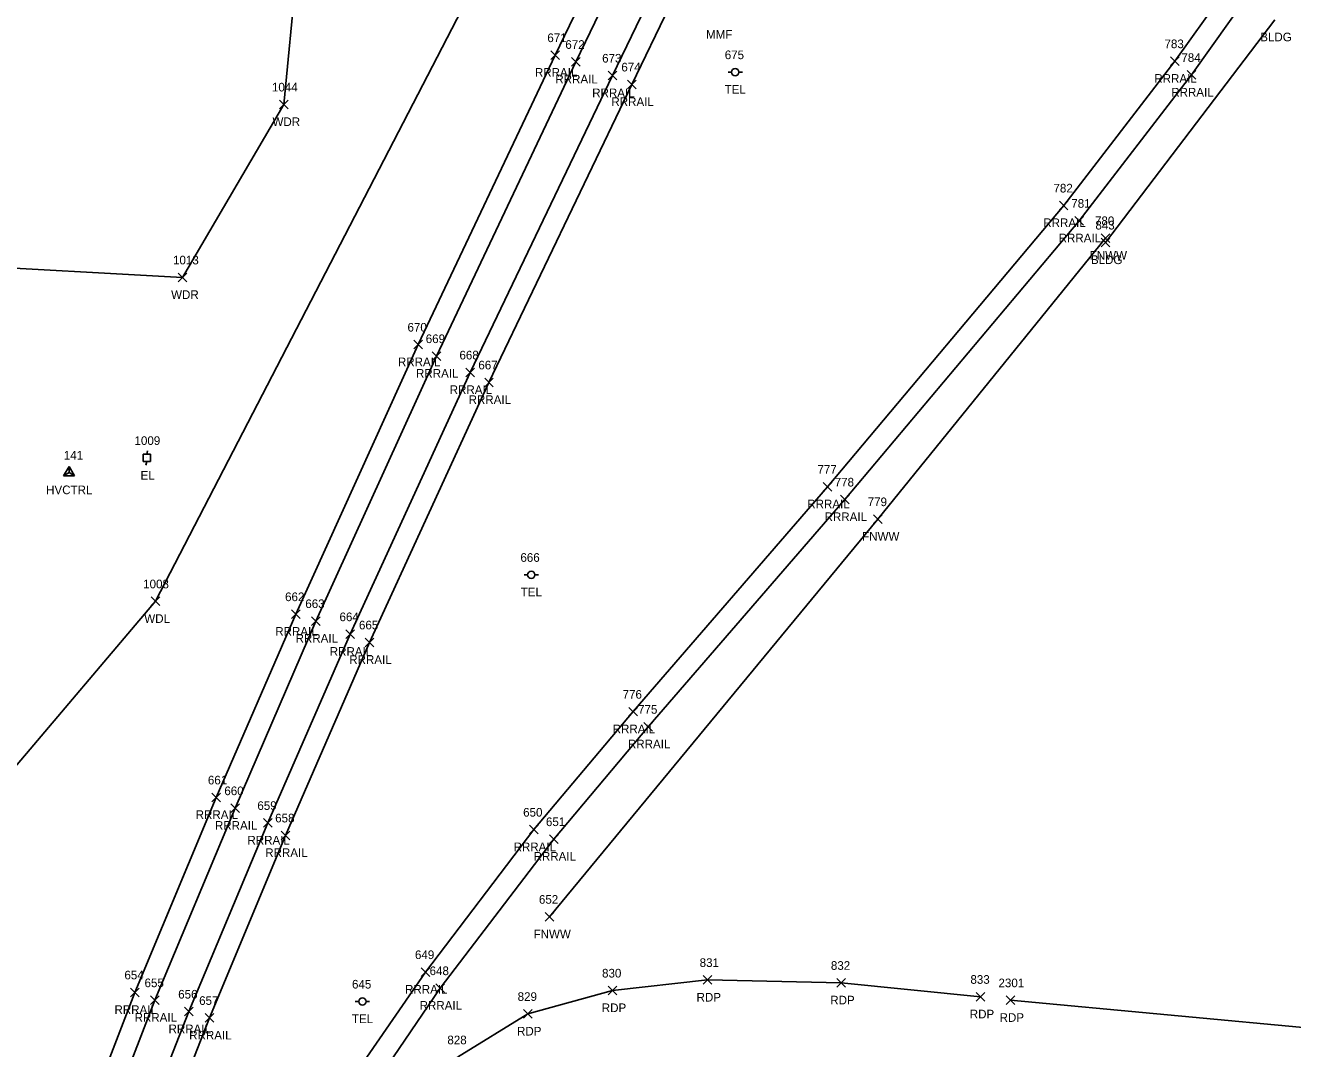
# Model space of a CAD drawing. Extents: x 1767353 to 1772625, y 740790 to 747702.
# Drawn here: x 1770332.7 to 1770625.6, y 742432.9 to 742669.5 of the extents above; entities that cross this region are included whole.
import ezdxf

# ---------------------------------------------------------------- set-up
doc = ezdxf.new("R2010")
doc.units = 0
for name, color, linetype in [('C_A', 7, 'Continuous'), ('C_I', 7, 'Continuous'), ('CPSM', 7, 'Continuous'), ('L_A', 7, 'Continuous'), ('L_I', 7, 'Continuous'), ('L_TIC', 7, 'Continuous'), ('LAWA', 7, 'Continuous'), ('LBC', 7, 'Continuous'), ('LFNC', 7, 'Continuous'), ('P_A', 7, 'Continuous'), ('P_I', 7, 'Continuous'), ('P_TIC', 7, 'Continuous'), ('PET', 7, 'Continuous'), ('R_A', 7, 'Continuous'), ('R_I', 7, 'Continuous'), ('R_TIC', 7, 'Continuous'), ('RR', 7, 'Continuous'), ('U_A', 7, 'Continuous'), ('U_I', 7, 'Continuous'), ('UEPT', 7, 'Continuous'), ('UP', 7, 'Continuous')]:
    doc.layers.add(name, color=color, linetype=linetype)

msp = doc.modelspace()

# ---------------------------------------------------------------- linework, layer by layer
at = {"layer": 'CPSM'}
for p, q in [((1770341.57, 742565.35), (1770342.82, 742567.52)), ((1770344.07, 742565.35), (1770342.82, 742567.52)), ((1770342.82, 742566.08), (1770342.82, 742567.52)), ((1770341.57, 742565.35), (1770342.82, 742566.08)), ((1770341.57, 742565.35), (1770344.07, 742565.35)), ((1770342.82, 742566.08), (1770342.82, 742566.08)), ((1770342.82, 742566.08), (1770344.07, 742565.35))]:
    msp.add_line(p, q, dxfattribs=at)
at = {"layer": 'L_TIC'}
for points in [[(1770391.48, 742650.21), (1770393.48, 742652.21)], [(1770393.48, 742650.21), (1770391.48, 742652.21)], [(1770581.39, 742619.31), (1770583.39, 742621.31)], [(1770583.39, 742619.31), (1770581.39, 742621.31)], [(1770581.39, 742618.29), (1770583.39, 742620.29)], [(1770583.39, 742618.29), (1770581.39, 742620.29)], [(1770368.05, 742610.22), (1770370.05, 742612.22)], [(1770370.05, 742610.22), (1770368.05, 742612.22)], [(1770528.77, 742554.32), (1770530.77, 742556.32)], [(1770530.77, 742554.32), (1770528.77, 742556.32)], [(1770361.8, 742535.32), (1770363.8, 742537.32)], [(1770363.8, 742535.32), (1770361.8, 742537.32)], [(1770452.83, 742462.37), (1770454.83, 742464.37)], [(1770454.83, 742462.37), (1770452.83, 742464.37)]]:
    msp.add_lwpolyline(points, dxfattribs=at)
at = {"layer": 'LAWA'}
for points in [[(1770306.48, 742507.29), (1770316.18, 742614.11), (1770369.05, 742611.22), (1770392.48, 742651.21), (1770395.28, 742680.85), (1770432.3, 742733.17), (1770478.55, 742800.68), (1770491.83, 742862.01), (1770523.03, 742843.62)], [(1770306.48, 742507.29), (1770329.16, 742496.59), (1770362.8, 742536.32), (1770458.24, 742720.87), (1770495.95, 742787.49), (1770523.03, 742843.62)]]:
    msp.add_lwpolyline(points, dxfattribs=at)
at = {"layer": 'LBC'}
msp.add_lwpolyline([(1770582.39, 742619.29), (1770621.54, 742670.81)], dxfattribs=at)
at = {"layer": 'LFNC'}
msp.add_lwpolyline([(1770453.83, 742463.37), (1770529.77, 742555.32), (1770582.39, 742620.31)], dxfattribs=at)
at = {"layer": 'P_TIC'}
for points in [[(1770489.36, 742447.75), (1770491.36, 742449.75)], [(1770491.36, 742447.75), (1770489.36, 742449.75)], [(1770467.46, 742445.31), (1770469.46, 742447.31)], [(1770469.46, 742445.31), (1770467.46, 742447.31)], [(1770520.27, 742447.09), (1770522.27, 742449.09)], [(1770522.27, 742447.09), (1770520.27, 742449.09)], [(1770552.51, 742443.86), (1770554.51, 742445.86)], [(1770554.51, 742443.86), (1770552.51, 742445.86)], [(1770559.4, 742443.06), (1770561.4, 742445.06)], [(1770561.4, 742443.06), (1770559.4, 742445.06)], [(1770447.87, 742439.9), (1770449.87, 742441.9)], [(1770449.87, 742439.9), (1770447.87, 742441.9)]]:
    msp.add_lwpolyline(points, dxfattribs=at)
at = {"layer": 'PET'}
for points in [[(1770243.74, 741939.41), (1770255.24, 741954.28), (1770270.92, 742018.28), (1770293.62, 742096.86), (1770309.99, 742145.51), (1770335.13, 742217.35), (1770370.55, 742306.75), (1770390.86, 742357.46), (1770403.22, 742384.01), (1770418.01, 742412.4), (1770432.62, 742430.87), (1770448.87, 742440.9), (1770468.46, 742446.31), (1770490.36, 742448.75), (1770521.27, 742448.09), (1770553.51, 742444.86)], [(1770560.4, 742444.06), (1770632.97, 742437.3)]]:
    msp.add_lwpolyline(points, dxfattribs=at)
at = {"layer": 'R_TIC'}
for points in [[(1770454.2, 742661.62), (1770456.2, 742663.62)], [(1770456.2, 742661.62), (1770454.2, 742663.62)], [(1770458.92, 742660.06), (1770460.92, 742662.06)], [(1770460.92, 742660.06), (1770458.92, 742662.06)], [(1770597.36, 742660.22), (1770599.36, 742662.22)], [(1770599.36, 742660.22), (1770597.36, 742662.22)], [(1770467.44, 742656.89), (1770469.44, 742658.89)], [(1770469.44, 742656.89), (1770467.44, 742658.89)], [(1770601.26, 742657.04), (1770603.26, 742659.04)], [(1770603.26, 742657.04), (1770601.26, 742659.04)], [(1770471.88, 742654.84), (1770473.88, 742656.84)], [(1770473.88, 742654.84), (1770471.88, 742656.84)], [(1770571.7, 742626.85), (1770573.7, 742628.85)], [(1770573.7, 742626.85), (1770571.7, 742628.85)], [(1770575.25, 742623.32), (1770577.25, 742625.32)], [(1770577.25, 742623.32), (1770575.25, 742625.32)], [(1770422.54, 742594.68), (1770424.54, 742596.68)], [(1770424.54, 742594.68), (1770422.54, 742596.68)], [(1770426.72, 742592.02), (1770428.72, 742594.02)], [(1770428.72, 742592.02), (1770426.72, 742594.02)], [(1770434.51, 742588.24), (1770436.51, 742590.24)], [(1770436.51, 742588.24), (1770434.51, 742590.24)], [(1770438.88, 742585.94), (1770440.88, 742587.94)], [(1770440.88, 742585.94), (1770438.88, 742587.94)], [(1770517.15, 742561.81), (1770519.15, 742563.81)], [(1770519.15, 742561.81), (1770517.15, 742563.81)], [(1770521.14, 742558.86), (1770523.14, 742560.86)], [(1770523.14, 742558.86), (1770521.14, 742560.86)], [(1770394.2, 742532.35), (1770396.2, 742534.35)], [(1770396.2, 742532.35), (1770394.2, 742534.35)], [(1770398.89, 742530.75), (1770400.89, 742532.75)], [(1770400.89, 742530.75), (1770398.89, 742532.75)], [(1770406.79, 742527.71), (1770408.79, 742529.71)], [(1770408.79, 742527.71), (1770406.79, 742529.71)], [(1770411.29, 742525.82), (1770413.29, 742527.82)], [(1770413.29, 742525.82), (1770411.29, 742527.82)], [(1770472.18, 742509.79), (1770474.18, 742511.79)], [(1770474.18, 742509.79), (1770472.18, 742511.79)], [(1770475.7, 742506.31), (1770477.7, 742508.31)], [(1770477.7, 742506.31), (1770475.7, 742508.31)], [(1770375.8, 742489.97), (1770377.8, 742491.97)], [(1770377.8, 742489.97), (1770375.8, 742491.97)], [(1770380.25, 742487.48), (1770382.25, 742489.48)], [(1770382.25, 742487.48), (1770380.25, 742489.48)], [(1770387.76, 742484.07), (1770389.76, 742486.07)], [(1770389.76, 742484.07), (1770387.76, 742486.07)], [(1770391.87, 742481.18), (1770393.87, 742483.18)], [(1770393.87, 742481.18), (1770391.87, 742483.18)], [(1770449.26, 742482.52), (1770451.26, 742484.52)], [(1770451.26, 742482.52), (1770449.26, 742484.52)], [(1770453.89, 742480.33), (1770455.89, 742482.33)], [(1770455.89, 742480.33), (1770453.89, 742482.33)], [(1770424.18, 742449.58), (1770426.18, 742451.58)], [(1770426.18, 742449.58), (1770424.18, 742451.58)], [(1770357.03, 742444.88), (1770359.03, 742446.88)], [(1770359.03, 742444.88), (1770357.03, 742446.88)], [(1770427.56, 742445.86), (1770429.56, 742447.86)], [(1770429.56, 742445.86), (1770427.56, 742447.86)], [(1770361.68, 742443.08), (1770363.68, 742445.08)], [(1770363.68, 742443.08), (1770361.68, 742445.08)], [(1770369.52, 742440.44), (1770371.52, 742442.44)], [(1770371.52, 742440.44), (1770369.52, 742442.44)], [(1770374.3, 742438.98), (1770376.3, 742440.98)], [(1770376.3, 742438.98), (1770374.3, 742440.98)]]:
    msp.add_lwpolyline(points, dxfattribs=at)
at = {"layer": 'RR'}
for points in [[(1770221.78, 741982.04), (1770226.9, 742005.14), (1770231.58, 742026.58), (1770238.97, 742057.62), (1770247.46, 742091.31), (1770255.17, 742120.86), (1770262.38, 742147.12), (1770270.79, 742177.04), (1770278.58, 742203.25), (1770285.57, 742226.22), (1770292.18, 742247.12), (1770303.7, 742282.6), (1770315.3, 742316.87), (1770330.35, 742359.31), (1770344.25, 742396.26), (1770362.68, 742444.08), (1770381.25, 742488.48), (1770399.89, 742531.75), (1770427.72, 742593.02), (1770459.92, 742661.06), (1770775.2, 743314.07), (1770996.39, 743772.66), (1771192.02, 744177.67), (1771329.71, 744462.72)], [(1770217.88, 741982.89), (1770224.63, 742006.05), (1770231.58, 742026.58), (1770242.49, 742057.3), (1770253.86, 742089.03), (1770263.22, 742117.76), (1770271, 742143.83), (1770279.57, 742174.49), (1770286.79, 742199.43), (1770293.9, 742223.08), (1770300.84, 742244.95), (1770311.67, 742279.15), (1770323.34, 742314.32), (1770337.98, 742356.11), (1770351.9, 742393.8), (1770370.52, 742441.44), (1770388.76, 742485.07), (1770407.79, 742528.71), (1770435.51, 742589.24), (1770468.44, 742657.89), (1770783.17, 743309.95), (1771004.51, 743768.91), (1771200.35, 744174.24), (1771337.45, 744458.43)], [(1770217.02, 741983.21), (1770222.11, 742006.18), (1770226.99, 742028.12), (1770234.33, 742059.23), (1770242.65, 742092.71), (1770250.33, 742121.94), (1770257.59, 742148.49), (1770265.95, 742178.19), (1770273.77, 742204.67), (1770280.68, 742227.53), (1770287.46, 742248.27), (1770299.11, 742284.6), (1770310.51, 742317.94), (1770325.96, 742361.53), (1770339.5, 742397.74), (1770358.03, 742445.88), (1770376.8, 742490.97), (1770395.2, 742533.35), (1770423.54, 742595.68), (1770455.2, 742662.62), (1770770.92, 743316.68), (1770991.9, 743774.87)], [(1770222.72, 741981.76), (1770229.32, 742004.36), (1770235.77, 742023.83), (1770247.09, 742055.41), (1770258.52, 742087.39), (1770268.11, 742116.55), (1770275.73, 742142.21), (1770291.55, 742198.01), (1770296.52, 742214.73), (1770305.48, 742243.41), (1770316.35, 742277.3), (1770328.03, 742312.86), (1770342.4, 742354.07), (1770356.59, 742392.13), (1770375.3, 742439.98), (1770392.87, 742482.18), (1770412.29, 742526.82), (1770439.88, 742586.94), (1770472.88, 742655.84), (1770787.34, 743307.49), (1771008.99, 743766.96)], [(1770271.52, 742143.69), (1770280.69, 742174.18), (1770289.74, 742198.6), (1770296.52, 742214.73), (1770308.93, 742241.95), (1770324.06, 742274.04), (1770340.68, 742308.04), (1770360.15, 742345.64), (1770381.03, 742382.61), (1770407.02, 742424.16), (1770425.18, 742450.58), (1770450.26, 742483.52), (1770473.18, 742510.79), (1770518.15, 742562.81), (1770572.7, 742627.85), (1770598.36, 742661.22), (1770630.52, 742706.14), (1770655.11, 742743.9), (1770674.5, 742775.55), (1770683.79, 742791.45), (1770706.15, 742833.16), (1770731.07, 742883.64), (1770775.22, 742979.87)], [(1770275.73, 742142.21), (1770285.7, 742173.47), (1770294.36, 742196.77), (1770301.28, 742213.26), (1770313.54, 742240.29), (1770328.52, 742271.98), (1770345.02, 742305.68), (1770363.97, 742342.43), (1770385.56, 742380.58), (1770410.92, 742420.89), (1770428.56, 742446.86), (1770454.89, 742481.33), (1770476.7, 742507.31), (1770522.14, 742559.86), (1770576.25, 742624.32), (1770602.26, 742658.04), (1770634.11, 742702.9), (1770659.93, 742742.21), (1770678.83, 742773.23), (1770687.73, 742788.35), (1770710.35, 742830.29), (1770735.06, 742880.72), (1770779.65, 742978.02)]]:
    msp.add_lwpolyline(points, dxfattribs=at)
at = {"layer": 'UEPT'}
for p, q in [((1770359.97, 742568.64), (1770359.97, 742570.3)), ((1770359.97, 742570.3), (1770361.64, 742570.3)), ((1770360.97, 742571.14), (1770360.8, 742570.3)), ((1770361.64, 742570.3), (1770361.64, 742568.64)), ((1770361.64, 742568.64), (1770359.97, 742568.64)), ((1770360.55, 742567.8), (1770360.8, 742568.64)), ((1770360.8, 742569.47), (1770360.8, 742569.47))]:
    msp.add_line(p, q, dxfattribs=at)
at = {"layer": 'UP'}
for p, q in [((1770495.12, 742658.68), (1770495.94, 742658.68)), ((1770496.77, 742658.68), (1770496.77, 742658.68)), ((1770498.44, 742658.68), (1770497.61, 742658.68)), ((1770497.61, 742658.68), (1770497.61, 742658.68)), ((1770498.44, 742658.68), (1770498.44, 742658.68)), ((1770447.99, 742542.44), (1770448.82, 742542.44)), ((1770449.65, 742542.44), (1770449.65, 742542.44)), ((1770451.32, 742542.44), (1770450.49, 742542.44)), ((1770450.49, 742542.44), (1770450.49, 742542.44)), ((1770451.32, 742542.44), (1770451.32, 742542.44)), ((1770408.97, 742443.76), (1770409.8, 742443.76)), ((1770410.63, 742443.76), (1770410.63, 742443.76)), ((1770412.3, 742443.76), (1770411.46, 742443.76)), ((1770411.46, 742443.76), (1770411.46, 742443.76)), ((1770412.3, 742443.76), (1770412.3, 742443.76))]:
    msp.add_line(p, q, dxfattribs=at)
for centre in [(1770496.77, 742658.68), (1770449.65, 742542.44), (1770410.63, 742443.76)]:
    msp.add_circle(centre, 0.833, dxfattribs=at)

# ---------------------------------------------------------------- texts
at = {"layer": 'C_A'}
msp.add_text('HVCTRL', height=2, dxfattribs=at).set_placement((1770337.52, 742561.08))
at = {"layer": 'C_I'}
msp.add_text('141', height=2, dxfattribs=at).set_placement((1770341.6, 742569.08))
at = {"layer": 'L_A'}
for s, p in [('MMF', (1770490.05, 742666.41)), ('BLDG', (1770618.13, 742665.81)), ('WDR', (1770389.84, 742646.21)), ('FNWW', (1770578.73, 742615.31)), ('BLDG', (1770578.99, 742614.29)), ('WDR', (1770366.41, 742606.22)), ('FNWW', (1770526.12, 742550.32)), ('WDL', (1770360.21, 742531.32)), ('FNWW', (1770450.18, 742458.37))]:
    msp.add_text(s, height=2, dxfattribs=at).set_placement(p)
at = {"layer": 'L_I'}
for s, p in [('1044', (1770389.71, 742654.21)), ('780', (1770579.94, 742623.31)), ('843', (1770580.03, 742622.29)), ('1013', (1770366.85, 742614.22)), ('779', (1770527.4, 742558.32)), ('1008', (1770359.95, 742539.32)), ('652', (1770451.42, 742466.37))]:
    msp.add_text(s, height=2, dxfattribs=at).set_placement(p)
at = {"layer": 'P_A'}
for p in [(1770487.85, 742443.75), (1770518.75, 742443.09), (1770465.95, 742441.31), (1770551, 742439.86), (1770557.89, 742439.06), (1770446.36, 742435.9)]:
    msp.add_text('RDP', height=2, dxfattribs=at).set_placement(p)
at = {"layer": 'P_I'}
for s, p in [('831', (1770488.57, 742451.75)), ('832', (1770518.9, 742451.09)), ('830', (1770466.01, 742449.31)), ('833', (1770551.15, 742447.86)), ('2301', (1770557.63, 742447.06)), ('829', (1770446.5, 742443.9)), ('828', (1770430.26, 742433.87))]:
    msp.add_text(s, height=2, dxfattribs=at).set_placement(p)
at = {"layer": 'R_A'}
for p in [(1770450.49, 742657.62), (1770455.22, 742656.06), (1770593.65, 742656.22), (1770463.73, 742652.89), (1770597.56, 742653.04), (1770468.17, 742650.84), (1770567.99, 742622.85), (1770571.54, 742619.32), (1770418.83, 742590.68), (1770423.01, 742588.02), (1770430.8, 742584.24), (1770435.17, 742581.94), (1770513.44, 742557.81), (1770517.44, 742554.86), (1770390.49, 742528.35), (1770395.18, 742526.75), (1770403.08, 742523.71), (1770407.58, 742521.82), (1770468.47, 742505.79), (1770471.99, 742502.31), (1770372.09, 742485.97), (1770376.54, 742483.48), (1770384.05, 742480.07), (1770388.16, 742477.18), (1770445.56, 742478.52), (1770450.18, 742476.33), (1770420.48, 742445.58), (1770423.85, 742441.86), (1770353.32, 742440.88), (1770357.97, 742439.08), (1770365.81, 742436.44), (1770370.59, 742434.98)]:
    msp.add_text('RRRAIL', height=2, dxfattribs=at).set_placement(p)
at = {"layer": 'R_I'}
for s, p in [('671', (1770453.36, 742665.62)), ('783', (1770596, 742664.22)), ('672', (1770457.52, 742664.06)), ('673', (1770466.03, 742660.89)), ('674', (1770470.47, 742658.84)), ('784', (1770599.9, 742661.04)), ('782', (1770570.34, 742630.85)), ('781', (1770574.46, 742627.32)), ('670', (1770421.04, 742598.68)), ('669', (1770425.26, 742596.02)), ('668', (1770433.05, 742592.24)), ('667', (1770437.42, 742589.94)), ('777', (1770515.79, 742565.81)), ('778', (1770519.78, 742562.86)), ('662', (1770392.75, 742536.35)), ('663', (1770397.43, 742534.75)), ('664', (1770405.33, 742531.71)), ('665', (1770409.83, 742529.82)), ('776', (1770470.76, 742513.79)), ('775', (1770474.34, 742510.31)), ('661', (1770374.91, 742493.97)), ('660', (1770378.71, 742491.48)), ('659', (1770386.34, 742488.07)), ('650', (1770447.77, 742486.52)), ('658', (1770390.46, 742485.18)), ('651', (1770453.04, 742484.33)), ('649', (1770422.77, 742453.58)), ('654', (1770355.62, 742448.88)), ('648', (1770426.15, 742449.86)), ('655', (1770360.27, 742447.08)), ('656', (1770368.05, 742444.44)), ('657', (1770372.89, 742442.98))]:
    msp.add_text(s, height=2, dxfattribs=at).set_placement(p)
at = {"layer": 'U_A'}
for s, p in [('TEL', (1770494.33, 742653.68)), ('EL', (1770359.34, 742564.47)), ('TEL', (1770447.21, 742537.44)), ('TEL', (1770408.19, 742438.76))]:
    msp.add_text(s, height=2, dxfattribs=at).set_placement(p)
at = {"layer": 'U_I'}
for s, p in [('675', (1770494.37, 742661.68)), ('1009', (1770357.95, 742572.47)), ('666', (1770447.14, 742545.44)), ('645', (1770408.22, 742446.76))]:
    msp.add_text(s, height=2, dxfattribs=at).set_placement(p)

doc.saveas('drawing.dxf')
